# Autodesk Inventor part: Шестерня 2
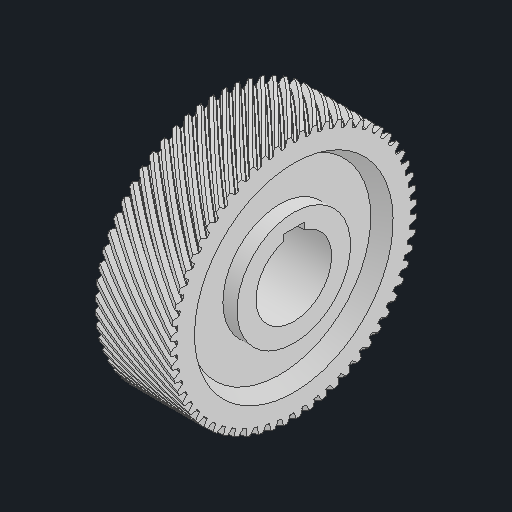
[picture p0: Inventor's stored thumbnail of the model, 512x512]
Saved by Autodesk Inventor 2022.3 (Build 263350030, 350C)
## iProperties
Created: 2020-09
Part Number: Шестерня 2
Material: Типовые
Document SubType Name: Modeling
Designer: Карташов
Density: 1 g/cm^3
Appearance: По умолчанию
Title: D:\мои документы\Ирина\_WorldSkills\2020_09 ФНЧ\Module A\GIVEN\Шестерня 2.stp
Author: Дом
Sending System: Autodesk Inventor 2021
Preprocessor: ST-DEVELOPER v18.1
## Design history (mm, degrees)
feature "Твердое тело2"
node "Твердое тело1"
